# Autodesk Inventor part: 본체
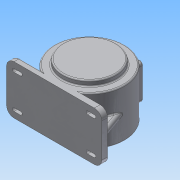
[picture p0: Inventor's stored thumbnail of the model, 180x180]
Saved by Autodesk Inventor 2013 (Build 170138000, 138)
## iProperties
Created: 2015-06
Part Number: 본체
Material: 알루미늄 6061
Document SubType Name: Modeling
Designer: dgall
Density: 2.71 g/cm^3
Mass: 3328.83 g
Surface Area: 2328.01 cm^2
Volume: 1228.35 cm^3
Author: dgall
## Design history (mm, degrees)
sketch "스케치1"
  geometry: L1 (-115, 59)-(115, 59); L2 (115, 59)-(115, -59); L3 (115, -59)-(-115, -59); L4 (-115, -59)-(-115, 59); 5 further points
  constraints: 8 end point, 4 midpoint, 2 horizontal alignment, 2 parallel, 2 vertical alignment, 1 horizontal, 1 perpendicular
  dimensions: "d0" = 230 distance of L1.start L1.end; "d2" = 118 distance of L1.end L2.end
extrude "돌출1" new body sketch "스케치1" distance "d3" = 14; taper "d4" = 0 deg
sketch "스케치2"
  geometry: L1 (14, -59)-(14, 59) reference; L2 (85, 59)-(85, -59); L3 (0, 59)-(0, -59) reference; L4 (85, 59)-(170, 59); L5 (170, 59)-(170, -59); L6 (170, -59)-(85, -59); L7 (162, -51)-(162, 51); L8 (162, 51)-(85, 51); L9 (85, -51)-(162, -51); L10 (116, 51)-(114.368, 47.5); L11 (85, 47.5)-(114.368, 47.5); L12 (85, 51)-(85, 47.5); 1 further point
  constraints: 20 end point, 4 parallel, 4 point on line, 3 perpendicular, 1 collinear, 1 horizontal alignment
  dimensions: "d5" = 85 distance between parallel lines of L3 L2; "d6" = 170 diameter of L5 L2; "d7" = 118 distance between parallel lines of L6 L4; "d8" = 118 distance of L3.start L3.end (derived); "d9" = 8 distance between parallel lines of L7 L5; "d10" = 102 distance between parallel lines of L9 L8; "d11" = 8 distance between parallel lines of L8 L4; "d36" = 115 deg angle of L8 L10; "d37" = 62 diameter of L10.start L2; "d38" = 3.5 distance between parallel lines of L11 L8
revolve "회전1" stored, may be unused: angle "d12" = 90 deg
sketch "스케치3"
  geometry: C1 r 65 at (115, 85); A1 r 85 centre (115, 85) between (161.733, 14) and (68.267, 14) reference; 1 further point
  constraints: 1 centre point, 1 coincident
  dimensions: "d13" = 130 diameter of C1
extrude "돌출2" join sketch "스케치3" distance "d15" = 13; taper "d16" = 0 deg
sketch "스케치4"
  geometry: C1 r 65 at (115, 85); A1 r 85 centre (115, 85) between (161.733, 14) and (68.267, 14) reference; 1 further point
  constraints: 1 centre point, 1 coincident
  dimensions: "d17" = 130 diameter of C1
extrude "돌출3" join sketch "스케치4" distance "d19" = 3; taper "d20" = 0 deg
sketch "스케치5"
  geometry: C1 r 65 at (0, 0) reference; C2 r 47.5 at (0, 0); 1 further point
  constraints: 1 centre point, 1 coincident
  dimensions: "d21" = 95 diameter of C2
extrude "돌출4" cut sketch "스케치5" distance "d23" = 20; taper "d24" = 0 deg
node "스케치6"
revolve "회전2" stored, may be unused: angle "d39" = 90 deg
sketch "스케치7" dims "d40" = 110
  geometry: C1 r 47.5 at (0, 0) reference; C2 r 65 at (0, 0) reference; 3 further points
  constraints: 2 vertical alignment, 1 coincident, 2 other
hole "구멍1" sketch "스케치7" at (0, 55) diameter "d42" = 3.242; stored, may be unused: countersink angle "d46" = 90 deg, drill point angle "d48" = 118 deg; dims "d43" = 13, "d44" = 3.6, "d45" = 2, "d47" = 15
sketch "스케치8"
  geometry: C1 r 29.368 at (0, 0) reference; C2 r 23.5 at (0, 0); C3 r 15 at (0, 0); 1 further point
  constraints: 2 centre point, 2 coincident
  dimensions: "d52" = 47 diameter of C2; "d54" = 30 diameter of C3
extrude "돌출5" cut sketch "스케치8" distance "d55" = 14; taper "d56" = 0 deg
extrude "돌출6" cut sketch "스케치8" distance "d57" = 17; taper "d58" = 0 deg
sketch "스케치9"
  geometry: L1 (-115, 59)-(115, 59) reference; L2 (-115, -59)-(-115, 59) reference; L3 (-97, 45)-(-81, 45); L4 (-97, 37)-(-81, 37); L5 (-81, 50)-(-97, 50); L6 (-97, 32)-(-81, 32); A1 r 4 centre (-97, 41) between (-97, 45) and (-97, 37); A2 r 4 centre (-81, 41) between (-81, 37) and (-81, 45); A3 r 9 centre (-97, 41) between (-97, 50) and (-97, 32); A4 r 9 centre (-81, 41) between (-81, 32) and (-81, 50); 1 further point
  constraints: 8 end point, 8 point on circle, 4 centre point, 4 tangent, 1 equal radius, 1 horizontal alignment, 3 other
  dimensions: "d59" = 18 distance from line of L1 A1.centre; "d60" = 18 distance from line of L2 A1.centre; "d61" = 16 distance of A2.centre A1.centre; "d62" = 8 diameter of A1; "d63" = 18 distance between parallel lines of L6 L5
extrude "돌출7" join sketch "스케치9" distance "d64" = 3; taper "d65" = 0 deg
sketch "스케치10"
  geometry: L1 (-81, 50)-(-97, 50) reference; L2 (-97, 32)-(-81, 32) reference; L3 (-97, 45)-(-81, 45); L4 (-81, 37)-(-97, 37); A1 r 9 centre (-97, 41) between (-97, 50) and (-97, 32) reference; A2 r 9 centre (-81, 41) between (-81, 32) and (-81, 50) reference; A3 r 4 centre (-81, 41) between (-81, 37) and (-81, 45); A4 r 4 centre (-97, 41) between (-97, 45) and (-97, 37); 1 further point
  constraints: 4 end point, 4 point on circle, 2 centre point, 3 other
  dimensions: "d66" = 8 distance between parallel lines of L4 L3
extrude "돌출8" cut sketch "스케치10" stored distance "d68" = 3; taper "d69" = 0 deg
node "작업 평면1"
sketch "스케치11"
  geometry: L1 (42.5, 42.5)-(-42.5, 42.5); L2 (-42.5, 42.5)-(-42.5, -42.5); L3 (-42.5, -42.5)-(42.5, -42.5); L4 (42.5, -42.5)-(42.5, 42.5); C1 r 35 at (0, 0); 5 further points
  constraints: 8 end point, 4 midpoint, 2 horizontal alignment, 2 parallel, 2 vertical alignment, 1 centre point, 1 coincident, 1 horizontal, 1 perpendicular
  dimensions: "d71" = 85 distance of L1.start L1.end; "d73" = 85 distance between parallel lines of L3 L1; "d74" = 70 diameter of C1
extrude "돌출9" join sketch "스케치11" stored distance "d75" = 3; taper "d76" = 0 deg
extrude "돌출10" cut sketch "스케치11" stored distance "d77" = 3; taper "d78" = 0 deg
sketch "스케치12"
  geometry: L1 (-42.5, 42.5)-(42.5, 42.5) reference; L2 (-42.5, -42.5)-(-42.5, 42.5) reference; 1 further point
  dimensions: "d81" = 7 distance from line of L2 point (-35.5, 35.5); "d82" = 7 distance from line of L1 point (-35.5, 35.5)
hole "구멍2" sketch "스케치12" at (-35.5, 35.5) diameter "d83" = 3.242; stored, may be unused: countersink angle "d87" = 90 deg, drill point angle "d89" = 118 deg; dims "d84" = 10, "d85" = 3.6, "d86" = 2, "d88" = 13
node "작업 평면2"
sketch "스케치13"
  geometry: L1 (68.267, 14)-(0, 14) reference; L2 (6, 14)-(30.13, 80.297); A1 r 85 centre (115, 85) between (161.733, 14) and (68.267, 14) reference; 1 further point
  constraints: 2 end point, 1 point on circle, 1 point on line
  dimensions: "d97" = 6 distance of L2.start L1.end; "d98" = 110 deg angle of L2 L1
feature "리브1" sketch "스케치13" dims "d99" = 1, "d100" = 15, "d101" = 0, "d102" = 0, "d103" = 1, "d104" = 1
fillet "모깎기1" dims "d105" = 3
fillet "모깎기2" dims "d106" = 18
fillet "모깎기3"
fillet "모깎기4"
fillet "모깎기5" dims "d107" = 7
fillet "모깎기6" dims "d108" = 3
fillet "모깎기7" dims "d109" = 3
fillet "모깎기8" dims "d110" = 3
chamfer "모따기1" distance "d111" = 1; stored, may be unused: second distance "d112" = 2, angle "d113" = 45 deg
fillet "모깎기9" dims "d114" = 0.3
fillet "모깎기10" dims "d115" = 3
chamfer "모따기2" distance "d116" = 1; stored, may be unused: second distance "d117" = 2, angle "d118" = 45 deg
fillet "모깎기11" dims "d119" = 3
fillet "모깎기12" dims "d120" = 3
node "솔리드1"
pattern_circular "원형 패턴1" dims angle "d50" = 360 deg
mirror "대칭1"
mirror "대칭2"
pattern_linear "직사각형 패턴1" dims "d92" = 71, "d95" = 71
mirror "대칭3"
other parameters: "d70" = -173, "d96" = -59
